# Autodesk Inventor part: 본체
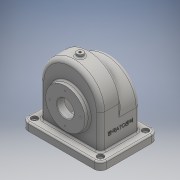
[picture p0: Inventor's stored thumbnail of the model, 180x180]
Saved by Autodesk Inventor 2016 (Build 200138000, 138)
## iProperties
Created: 2017-11
Part Number: 본체
Material: 일반
Document SubType Name: Modeling
Designer: USER
Density: 1 g/cm^3
Appearance: 기본값
Author: USER
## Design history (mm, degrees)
sketch "스케치1"
  geometry: L1 (-58, 0)-(-58, -80); L2 (-58, -80)-(58, -80); L3 (58, -80)-(58, 0); A1 r 58 centre (0, 0) between (58, 0) and (-58, 0); 2 further points
  constraints: 6 end point, 2 point on circle, 2 tangent, 1 centre point, 1 coincident, 1 horizontal alignment, 1 midpoint, 1 perpendicular, 1 vertical
  dimensions: "d0" = 116 diameter of A1; "d2" = 116 distance of L1.end L2.end; "d3" = 80 distance from line of L2 point (0, 0)
extrude "돌출1" new body sketch "스케치1" distance "d4" = 38; taper "d5" = 0 deg
sketch "스케치2"
  geometry: L1 (58, 80)-(-58, 80) reference; L2 (58, 0)-(58, 80) reference; L3 (58, 23)-(58, 80); L4 (58, 80)-(-58, 80); L5 (-58, 80)-(-58, 0) reference; L6 (-58, 23)-(-58, 80); A1 r 58 centre (0, 23) between (-58, 23) and (58, 23); 1 further point
  constraints: 6 end point, 2 collinear, 2 point on circle, 1 centre point, 1 vertical alignment
  dimensions: "d7" = 57 distance from line of L1 A1.centre; "d9" = 58 radius of A1; "d10" = 57 distance of L3.start L1.start
extrude "돌출2" join sketch "스케치2" distance "d11" = 38; taper "d12" = 0 deg
feature "쉘1" dims "d13" = 5
sketch "스케치3"
  geometry: L1 (133, -17)-(-17, -17); L2 (-17, -17)-(-17, 93); L3 (-17, 93)-(133, 93); L4 (133, 93)-(133, -17); L5 (5, 71)-(111, 71) reference; L6 (111, 71)-(111, 5) reference; L7 (111, 5)-(5, 5) reference; L8 (5, 5)-(5, 71) reference; L9 (116, 0)-(0, 0) reference; L10 (116, 0)-(116, 76) reference; L11 (0, 76)-(116, 76) reference; L12 (0, 0)-(0, 76) reference; 5 further points
  constraints: 8 end point, 4 midpoint, 2 parallel, 1 horizontal, 1 horizontal alignment, 1 perpendicular, 1 vertical alignment
  dimensions: "d14" = 150 distance of L1.start L1.end; "d15" = 110 distance of L1.end L2.end
extrude "돌출3" join sketch "스케치3" distance "d16" = 15; taper "d17" = 0 deg
sketch "스케치4"
  geometry: L1 (75, 80)-(-75, 80) reference; C1 r 31 at (0, 15); 1 further point
  constraints: 1 centre point, 1 vertical alignment
  dimensions: "d18" = 62 diameter of C1; "d19" = 65 distance from line of L1 C1.centre
extrude "돌출4" join sketch "스케치4" distance "d20" = 10; taper "d21" = 0 deg
sketch "스케치5"
  geometry: L1 (-75, -80)-(75, -80) reference; C1 r 37.5 at (0, -15); 1 further point
  constraints: 1 centre point, 1 vertical alignment
  dimensions: "d22" = 75 diameter of C1; "d23" = 65 distance from line of L1 C1.centre
extrude "돌출5" join sketch "스케치5" distance "d24" = 9; taper "d25" = 0 deg
sketch "스케치6"
  geometry: L1 (75, 65)-(-75, 65) reference; C1 r 16 at (0, 0); 1 further point
  constraints: 1 centre point, 1 vertical alignment
  dimensions: "d26" = 32 diameter of C1; "d27" = 65 distance from line of L1 C1.centre
extrude "돌출6" cut sketch "스케치6" distance "d28" = 107.75; taper "d29" = 0 deg
sketch "스케치7"
  geometry: C1 r 16 at (0, 0) reference; C2 r 37.5 at (0, 0) reference; 2 further points
  constraints: 1 vertical alignment
  dimensions: "d30" = 29 distance of C1.centre point (0, 29)
hole "구멍1" sketch "스케치7" at (0, 29) diameter "d31" = 2.459; stored, may be unused: countersink angle "d35" = 90 deg, drill point angle "d37" = 118 deg; dims "d32" = 6, "d33" = 4, "d34" = 2, "d36" = 8
sketch "스케치8"
  geometry: C1 r 16 at (0, 0) reference; C2 r 31 at (0, 0) reference; 2 further points
  constraints: 1 vertical alignment
  dimensions: "d42" = 26 distance of point (0, -26) C1.centre
hole "구멍2" sketch "스케치8" at (0, -26) diameter "d43" = 2.459; stored, may be unused: countersink angle "d47" = 90 deg, drill point angle "d49" = 118 deg; dims "d44" = 6, "d45" = 4, "d46" = 2, "d48" = 8
sketch "스케치9"
  geometry: L1 (-133, 93)-(-133, -17) reference; L2 (17, 93)-(-133, 93) reference; L3 (17, -17)-(17, 93) reference; L4 (-133, -17)-(17, -17) reference; C1 r 6 at (-121, 81); C2 r 6 at (5, 81); C3 r 6 at (5, -5); C4 r 6 at (-121, -5); 1 further point
  constraints: 4 centre point, 2 horizontal alignment, 2 vertical alignment
  dimensions: "d53" = 12 diameter of C1; "d54" = 12 diameter of C2; "d55" = 12 diameter of C3; "d56" = 12 diameter of C4; "d57" = 12 distance from line of L1 C1.centre; "d58" = 12 distance from line of L2 C1.centre; "d59" = 12 distance from line of C3.centre L3; "d60" = 12 distance from line of L4 C3.centre
fillet "모깎기1" dims "d61" = 12
fillet "모깎기2" dims "d62" = 8
fillet "모깎기3" dims "d63" = 3
extrude "돌출7" cut sketch "스케치9" distance "d64" = 5; taper "d65" = 0 deg
sketch "스케치10"
  geometry: C1 r 6 at (126, -98) reference; C2 r 2.5 at (126, -98); C3 r 6 at (0, -12) reference; C4 r 2.5 at (0, -12); C5 r 2.5 at (0, -98); C6 r 2.5 at (126, -12); 1 further point
  constraints: 4 centre point, 2 coincident, 2 horizontal alignment, 2 vertical alignment
  dimensions: "d66" = 5 diameter of C2; "d67" = 5 diameter of C4; "d68" = 5 diameter of C5; "d69" = 5 diameter of C6
extrude "돌출8" cut sketch "스케치10" distance "d70" = 114.25; taper "d71" = 0 deg
fillet "모깎기4" dims "d72" = 3
fillet "모깎기5" dims "d73" = 3
node "작업 평면1"
sketch "스케치11"
  geometry: L1 (113, -93)-(13, -93) reference; L2 (138, -12)-(138, -98) reference; C1 r 6 at (63, -74); 1 further point
  constraints: 1 centre point
  dimensions: "d75" = 12 diameter of C1; "d76" = 19 distance from line of L1 C1.centre; "d77" = 75 distance from line of C1.centre L2
extrude "돌출9" join sketch "스케치11" distance "d78" = 7.5; taper "d79" = 0 deg
fillet "모깎기6" dims "d80" = 3
sketch "스케치12"
  geometry: C1 r 6 at (0, 0) reference; 2 further points
  constraints: 1 coincident
hole "구멍3" sketch "스케치12" at (0, 0) diameter "d81" = 4.459; stored, may be unused: countersink angle "d85" = 90 deg, drill point angle "d87" = 118 deg; dims "d82" = 10, "d83" = 4, "d84" = 2, "d86" = 24.5469
fillet "모깎기7" dims "d88" = 3
fillet "모깎기8" dims "d89" = 3
sketch "스케치13"
  geometry: L1 (-23, -35)-(39, -35) reference; L2 (57, -40)-(57, -52) reference; 1 further point
  constraints: 1 other
  dimensions: "d90" = 38 distance from line of L1 point (17, 3); "d91" = 40 distance from line of L2 point (17, 3)
feature "엠보싱1" sketch "스케치13" dims "d92" = 0.5, "d93" = 0
chamfer "모따기1" distance "d94" = 1; stored, may be unused: second distance "d95" = 2, angle "d96" = 45 deg
node "솔리드1"
pattern_circular "원형 패턴1" dims angle "d39" = 360 deg
pattern_circular "원형 패턴2" dims angle "d51" = 360 deg
node "투영된 루프1"
node "투영된 루프2"
node "투영된 루프3"
node "투영된 루프4"
other parameters: "d6" = 116, "d74" = -144
